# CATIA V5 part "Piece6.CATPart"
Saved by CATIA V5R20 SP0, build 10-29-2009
Part number: Piece6
Bounding box of the stored display mesh (mm): x -2 to 2, y 8.992 to 76.97, z 21.42 to 41.485
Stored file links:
  D:\Dropbox\IAO_2012\IAO_2012_815_gcordenod\gcordenod\Piece6.CATPart
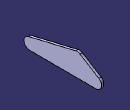
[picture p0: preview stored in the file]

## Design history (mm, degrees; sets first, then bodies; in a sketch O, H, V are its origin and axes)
Body1 (main body)
  Plane1: stored without definition
  Point1 "E": stored without definition
  Point2 "D": stored without definition
  Point3 "C": stored without definition
  Line1: stored without definition
  Sketch1 on Plane1, origin (0, 0, 0), H (0, 1, 0), V (0, 0, 1)
    line L1 (68.5886, 21.4266) -> (13.9811, 21.5376)
    arc A1 centre (13.9912, 26.5376) radius 5 from (13.9811, 21.5376) to (12.88, 31.4126) cw
    line L2 (12.88, 31.4126) -> (54.4203, 41.3484)
    arc A2 centre (55.5834, 36.4855) radius 5 from (54.4203, 41.3484) to (58.2001, 40.7461) cw
    line L3 (58.2001, 40.7461) -> (74.5891, 30.6803)
    arc A3 centre (71.9723, 26.4197) radius 5 from (74.5891, 30.6803) to (71.9621, 21.4197) cw
    point P10 (71.9621, 21.4197)
    line L4 (71.9621, 21.4197) -> (68.5886, 21.4266)
    reference projected point E1 (13.9912, 26.5376) from Point1
    reference projected point E2 (55.5834, 36.4855) from Point2
    reference projected point E3 (71.9723, 26.4197) from Line1
    radius A1 = 5
    radius A3 = 5
    radius A2 = 5
    tangency: A1 L1, A2 L2, A3 L3, L4 A1, A2 L3, A3 L4
    coincidence: P10 L1
    concentricity: E1 A1, E2 A2, E3 A3
  Pad1: profile Sketch1, direction (1, 0, 0), length 2
  Point4 "D": stored without definition
  DatumCurve1
  DatumSurface1
  Point5 "E": stored without definition
  Point6 "C": stored without definition
  Line2: stored without definition
  Sketch2 on start face of Pad1, origin (0, 0, 0), H (0, -1, 0), V (0, 0, 1)
    circle A1 centre (-55.5834, 36.4855) radius 1.5
    point P1 (-55.5834, 36.4855)
    reference projected point E1 (-55.5834, 36.4855) from Point4
    reference projected circle E2 centre (-55.5834, 36.4855) radius 1.5 from edge of DatumCurve1
    circle A2 centre (-13.9912, 26.5376) radius 1.9777
    point P2 (-13.9912, 26.5376)
    circle A3 centre (-71.9723, 26.4197) radius 1.9515
    reference projected point E3 (-13.9912, 26.5376) from Point5
    reference projected point E4 (-71.9723, 26.4197) from Line2
    radius A2 = 1.9777
    radius A3 = 1.9515
    coincidence: P1 E1, A1 E2, P2 E3
    concentricity: E4 A3
  Pad2: profile Sketch2, direction (-1, 0, 0), length 2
